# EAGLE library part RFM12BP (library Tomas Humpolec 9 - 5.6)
RFM12BP UNIVERSAL ISM BAND FSK TRANSCEIVER MODULE WITH 500mW OUTPUT POWER General Introduction RFM12BP is a low costing ISM band transceiver module implemented with 500mW output power. It works signal ranges from 433/868/915MHZ bands, The SPI interface is used to communicate with microcontroller for parameter setting. Features: - High output power with 500mW - High input sensitivity with -116dBm - Low costing, high performance and price ratio - PLL and zero IF technology - Fast PLL lock time - High resolution PLL with 2.5 KHz step - High data rate (up to 115.2 kbps with internal demodulator,with external RC filter highest data rate is 256 kbps) - 50 OHM antenna input/output - Programmable TX power - Programmable TX frequency deviation (from 15 to 240 KHz) - Programmable receiver bandwidth (from 67 to 400 kHz) - Analog and digital signal strength indicator (ARSSI/DRSSI) - Automatic frequency control (AFC) - Data quality detection (DQD) - Internal data filtering and clock recovery - RX synchron pattern recognition - SPI compatible serial control interface - Clock and reset signal output for external MCU use - 16 bit RX Data FIFO - Two 8 bit TX data registers - Standard 10 MHz crystal reference - Wakeup timer - 2.2V ? 3.8V power supply for FSK IC, 12V power supply for power amplifier - Standby current less than 0.3uA - Supports very short packets (down to 3 bytes) Typical Application: - Remote control - Remote sensor - Wireless data collection - Home security system - Toys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
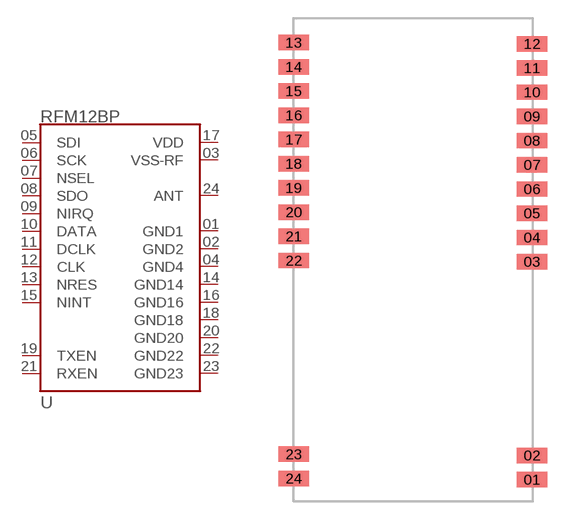
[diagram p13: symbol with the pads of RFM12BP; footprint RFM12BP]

Designator prefix -

## RFM12BP  [RFM12BP]
01  GND1  pwr
02  GND2  pwr
03  VSS-RF  pwr
04  GND4  pwr
05  SDI  in
06  SCK  in
07  NSEL  in
08  SDO  out
09  NIRQ  out
10  DATA
11  DCLK
12  CLK  out
13  NRES
14  GND14  pwr
15  NINT
16  GND16  pwr
17  VDD  pwr
18  GND18  pwr
19  TXEN  in
20  GND20  pwr
21  RXEN  in
22  GND22  pwr
23  GND23  pwr
24  ANT  out

## Footprint RFM12BP (pad centres in mm)
smd 2.54 x 1.27: 01 19.685,1.81; 02 19.685,3.81; 03 19.685,19.81; 04 19.685,21.81; 05 19.685,23.81; 06 19.685,25.81; 07 19.685,27.81; 08 19.685,29.81; 09 19.685,31.81; 10 19.685,33.81; 11 19.685,35.81; 12 19.685,37.81; 13 0,37.905; 14 0,35.905; 15 0,33.905; 16 0,31.905; 17 0,29.905; 18 0,27.905; 19 0,25.905; 20 0,23.905; 21 0,21.905; 22 0,19.905; 23 0,3.905; 24 0,1.905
